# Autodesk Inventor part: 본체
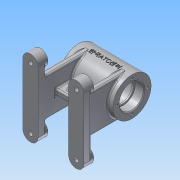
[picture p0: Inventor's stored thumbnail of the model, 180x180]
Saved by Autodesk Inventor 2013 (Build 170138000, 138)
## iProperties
Created: 2015-11
Part Number: 본체
Material: 알루미늄 6061
Document SubType Name: Modeling
Designer: Administrator
Density: 2.71 g/cm^3
Mass: 373.368 g
Surface Area: 453.781 cm^2
Volume: 137.774 cm^3
Author: Administrator
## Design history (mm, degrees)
sketch "스케치1"
  geometry: L1 (35, 0)-(-35, 0); L2 (-35, 25)-(35, 25); L3 (35, 25)-(35, 16); L4 (35, 16)-(23, 16); L5 (23, 16)-(23, 14); L6 (23, 14)-(21, 14); L7 (21, 14)-(21, 20); L8 (21, 20)-(-21, 20); L9 (-21, 20)-(-21, 14); L10 (-21, 14)-(-23, 14); L11 (-23, 14)-(-23, 16); L12 (-23, 16)-(-35, 16); L13 (-35, 16)-(-35, 25); 2 further points
  constraints: 26 end point, 10 parallel, 2 perpendicular, 1 coincident, 1 horizontal, 1 midpoint, 1 vertical alignment
  dimensions: "d1" = 70 distance of L1.start L1.end; "d3" = 70 distance of L2.start L2.end; "d5" = 32 diameter of L12 L1; "d6" = 50 diameter of L2 L1; "d7" = 28 diameter of L10 L1; "d8" = 32 diameter of L4 L1; "d9" = 28 diameter of L6 L1; "d10" = 40 diameter of L8 L1; "d11" = 2 distance between parallel lines of L9 L11; "d12" = 2 distance between parallel lines of L7 L5; "d13" = 12 distance between parallel lines of L13 L11; "d14" = 12 distance between parallel lines of L3 L5
revolve "회전1" sketch "스케치1" stored, may be unused: angle "d15" = 90 deg
chamfer "모따기1" distance "d16" = 1; stored, may be unused: second distance "d17" = 2, angle "d18" = 45 deg
fillet "모깎기1" dims "d19" = 0.3
node "작업 평면1"
sketch "스케치3"
  geometry: L1 (40, -40)-(40, 40); L2 (-20, 40)-(-20, -40); L3 (20, 40)-(20, -40); L4 (-40, -40)-(-40, 40); A1 r 10 centre (30, 40) between (40, 40) and (20, 40); A2 r 10 centre (-30, 40) between (-20, 40) and (-40, 40); A3 r 10 centre (-30, -40) between (-20, -40) and (-40, -40); A4 r 10 centre (30, -40) between (40, -40) and (20, -40); 2 further points
  constraints: 8 end point, 8 point on circle, 7 tangent, 4 centre point, 3 equal radius, 3 horizontal alignment, 2 vertical alignment, 1 midpoint, 1 vertical
  dimensions: "d33" = 20 diameter of A4; "d36" = 40 distance from line of L1 point (0, 0); "d37" = 40 distance from line of L4 point (0, 0); "d38" = 80 distance of A3.centre A2.centre
extrude "돌출3" join sketch "스케치3" distance "d39" = 10; taper "d40" = 0 deg
extrude "돌출4" join sketch "스케치3" distance "d41" = 13; taper "d42" = 0 deg
sketch "스케치4"
  geometry: L1 (40, -40)-(40, 40) reference; L2 (20, -25)-(20, 25); L3 (20, 25)-(28, 25); L4 (28, 25)-(28, -25); L5 (28, -25)-(20, -25); 2 further points
  constraints: 8 end point, 2 parallel, 1 horizontal alignment, 1 midpoint, 1 perpendicular
  dimensions: "d44" = 50 distance of L2.start L2.end; "d46" = 20 distance from line of L2 point (0, 0); "d47" = 8 distance of L2.end L3.end; "d48" = 50 distance of L3.end L4.end
extrude "돌출5" join sketch "스케치4" stored distance "d49" = 13; taper "d50" = 0 deg
node "작업 평면2"
sketch "스케치6"
  geometry: L1 (20, -4)-(-20, -4); L2 (-20, -4)-(-20, 4); L3 (-20, 4)-(20, 4); L4 (20, 4)-(20, -4); L5 (20, -4)-(-20, 4); L6 (-20, -4)-(20, 4); 1 further point
  constraints: 12 end point, 2 midpoint, 2 parallel, 1 horizontal, 1 perpendicular
  dimensions: "d54" = 8 distance between parallel lines of L1 L3; "d56" = 40 distance between parallel lines of L2 L4
extrude "돌출6" join sketch "스케치6" stored distance "d57" = 13; taper "d58" = 0 deg
sketch "스케치7"
  geometry: L1 (0, 20.322)-(40, 20.322) reference; L2 (12, 13.5)-(28, 13.5); L3 (28, 6.5)-(12, 6.5); L4 (60, -23)-(40, -23) reference; A1 r 3.5 centre (12, 10) between (12, 13.5) and (12, 6.5); A2 r 3.5 centre (28, 10) between (28, 6.5) and (28, 13.5); 2 further points
  constraints: 4 end point, 4 point on circle, 3 tangent, 2 centre point, 1 horizontal alignment, 1 midpoint, 1 parallel, 1 vertical alignment
  dimensions: "d59" = 7 diameter of A1; "d60" = 7 diameter of A2; "d61" = 33 distance from line of A2.centre L4; "d62" = 23 dimension on A1 A2
extrude "돌출7" cut sketch "스케치7" stored distance "d63" = 13; taper "d64" = 0 deg
node "작업 평면3"
sketch "스케치8"
  geometry: C1 r 5 at (0, 0); 1 further point
  constraints: 1 centre point, 1 coincident
  dimensions: "d66" = 10 diameter of C1
extrude "돌출8" join sketch "스케치8" stored distance "d67" = 13; taper "d68" = 0 deg
sketch "스케치9"
  geometry: L1 (-45, 4)-(-38.5, 4) reference; L2 (-38.5, 4)-(-38.5, -4) reference; L3 (-38.5, -4)-(-45, -4) reference; L4 (-45, -4)-(-45, 4) reference; L5 (-31.5, 4)-(-24.678, 4) reference; L6 (24.495, 5)-(28, 5) reference; L7 (28, 5)-(28, -5) reference; L8 (28, -5)-(24.495, -5) reference; L9 (-24.678, -4)-(-31.5, -4) reference; L10 (-31.5, -4)-(-31.5, 4) reference; L11 (0, 0)-(-24.249, -14); L12 (0, 0)-(-7.726, 0); C1 r 20 at (0, 0) reference; A1 r 25 centre (0, 0) between (24.495, 5) and (-24.678, 4) reference; A2 r 25 centre (0, 0) between (-24.678, -4) and (24.495, -5) reference; 1 further point
  constraints: 4 end point, 1 perpendicular
  dimensions: "d70" = 28 distance of L11.start L11.end; "d71" = 30 deg angle of L12 L11
  node "절단 모서리 투영1"
node "작업 평면4"
sketch "스케치10"
  geometry: C1 r 6 at (0, 0); 1 further point
  constraints: 1 centre point, 1 coincident
  dimensions: "d72" = 12 diameter of C1
extrude "돌출9" join sketch "스케치10" stored distance "d73" = 13; taper "d74" = 0 deg
hole "구멍1" diameter "d77" = 6; stored, may be unused: countersink angle "d81" = 90 deg, drill point angle "d83" = 118 deg; dims "d75" = 10, "d76" = 10, "d78" = 6, "d79" = 12, "d80" = 4, "d82" = 8
fillet "모깎기2" dims "d84" = 0.3
chamfer "모따기2" distance "d85" = 1; stored, may be unused: second distance "d86" = 2, angle "d87" = 45 deg
hole "구멍2" diameter "d90" = 5.188; stored, may be unused: countersink angle "d94" = 90 deg, drill point angle "d96" = 118 deg; dims "d88" = 10, "d89" = 10, "d91" = 6, "d92" = 1, "d93" = 4, "d95" = 8
hole "구멍3" diameter "d99" = 5.188; stored, may be unused: countersink angle "d103" = 90 deg, drill point angle "d105" = 118 deg; dims "d97" = 10, "d98" = 10, "d100" = 6, "d101" = 1, "d102" = 4, "d104" = 8
sketch "스케치11"
  geometry: C1 r 25 at (0, 0) reference; 1 further point
  constraints: 1 vertical alignment
  dimensions: "d106" = 20 distance of point (0, 20) C1.centre
hole "구멍4" sketch "스케치11" at (0, 20) diameter "d107" = 3.242; stored, may be unused: countersink angle "d111" = 90 deg, drill point angle "d113" = 118 deg; dims "d108" = 8, "d109" = 1, "d110" = 4, "d112" = 10
fillet "모깎기3" dims "d117" = 2
fillet "모깎기4" dims "d118" = 3
node "작업 평면5"
sketch "스케치12"
  geometry: L1 (-35, -25)-(-35, 25) reference; L2 (-35, 25)-(35, 25) reference; 2 further points
  constraints: 1 other
  dimensions: "d119" = 35 distance from line of point (0, 0) L1; "d120" = 25 distance from line of point (0, 0) L2
feature "엠보싱1" sketch "스케치12" dims "d1" = 70, "d121" = 0.5, "d122" = 0
node "솔리드1"
mirror "대칭1"
mirror "대칭2"
mirror "대칭3"
pattern_circular "원형 패턴1" dims angle "d115" = 360 deg
mirror "대칭4"
other parameters: "d20" = -68, "d53" = -45, "d65" = 28
